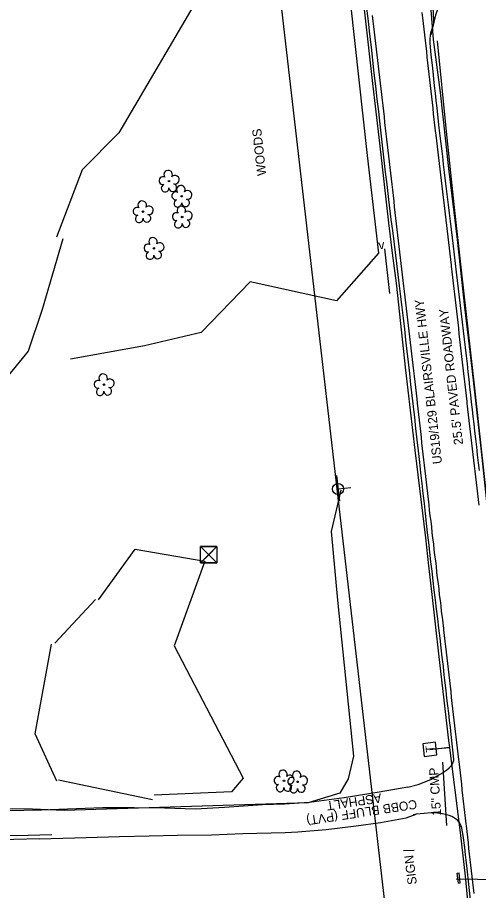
# Model space of a CAD drawing. Extents: x 472260 to 482161, y 489063 to 507124.
# Drawn here: x 478065.1 to 478267.5, y 496195.4 to 496579.2 of the extents above; entities that cross this region are included whole.
import ezdxf

# ---------------------------------------------------------------- set-up
doc = ezdxf.new("R2010")
doc.units = 0
for name, color, linetype in [('Exist Structure Minor Drop Inlet Cogo Elevation', 7, 'Continuous'), ('Exist Structure Minor Pipes CMP 60 Inch Cogo Number', 7, 'Continuous'), ('Prop Drainage Structure Catch Basin Convert From Junction Box Label', 7, 'Continuous'), ('Prop Drainage Structure Catch Basin Grate 840 03E CELL', 7, 'Continuous'), ('Prop Drainage Structure Drop Inlet Grate 2 Narrow Slots and Sag Grates 840 24 CELL', 7, 'Continuous'), ('Prop Drainage Structure Drop Inlet Grate 2 Wide Slots and Flat Grates 840 20 Label', 7, 'Continuous'), ('Prop Drainage Structure Drop Inlet Grate 2 Wide Slots and Sag Grates 840 22 Label', 7, 'Continuous'), ('Prop Drainage Structure Pipe Plug CELL', 7, 'Continuous'), ('Prop Drainage Structure Pipe RCP 18in Class IV Label', 7, 'Continuous'), ('Prop Drainage Structure Pipe RCP 48in Class IV', 7, 'Continuous'), ('Prop Drainage Structure Pipe RCP 66in Class III', 7, 'Continuous'), ('Prop Drainage Structure Pipe RCP 66in Class IV', 7, 'Continuous'), ('Prop Drainage Structure Pipe Stub Out CELL', 7, 'Continuous'), ('Prop Drainage Structure Pipe Welded Steel 66in', 7, 'Continuous'), ('Prop Drainage Structure Plot Symbol 20 Scale', 7, 'Continuous'), ('Prop Drainage Structure Plot Symbol 50 Scale', 7, 'Continuous'), ('Prop Drainage Structure Plot Symbol 50 Scale CELL', 7, 'Continuous'), ('Prop Drainage Structure Tops and Inverts LABEL', 7, 'Continuous'), ('Prop Earthen Structure Base Ditch Lateral Detail Label', 7, 'Continuous'), ('Prop Earthen Structure Ditch Flow Line', 7, 'Continuous'), ('Prop Erosion Rip Rap Class B', 7, 'Continuous'), ('Prop Erosion Rip Rap Class II', 7, 'Continuous'), ('Prop Erosion Rip Rap Pad at Outlet Label', 7, 'Continuous'), ('Prop Erosion Rip Rap Single Stone CELL', 7, 'Continuous')]:
    doc.layers.add(name, color=color, linetype=linetype)

msp = doc.modelspace()

# ---------------------------------------------------------------- linework, layer by layer
at = {"layer": 'Exist Structure Minor Drop Inlet Cogo Elevation'}
msp.add_line((478244.7, 496030.8), (478097.62, 497308.11), dxfattribs=at)
at = {"layer": 'Exist Structure Minor Pipes CMP 60 Inch Cogo Number'}
msp.add_lwpolyline([(477932.09, 496214.52), (477944.82, 496215.37), (477961.02, 496215.65), (477978.35, 496216), (477999.41, 496216.05), (478022.93, 496218.78), (478044.03, 496220.19), (478064.48, 496219.57), (478080.22, 496219.93)], dxfattribs=at)
at = {"layer": 'Prop Drainage Structure Catch Basin Convert From Junction Box Label'}
for p, q in [((478246.1, 496257.34), (478254.92, 496258.36)), ((478254.96, 496258.08), (478246.1, 496257.34)), ((478259.57, 496220.81), (478254.96, 496258.08))]:
    msp.add_line(p, q, dxfattribs=at)
for points in [[(478254.92, 496258.36), (478254.53, 496261.32), (478250.25, 496298.09), (478247.03, 496326.76), (478245.65, 496338.15), (478244.35, 496350.45), (478239.77, 496389), (478235.62, 496424.12), (478231.44, 496462.29), (478229.82, 496475.54), (478228.2, 496488.92), (478224.18, 496523.91), (478220.99, 496551.51), (478217.77, 496580.16), (478214.42, 496608.18), (478212.13, 496627.19), (478209.7, 496647.59)], [(478283.71, 496258.37), (478282.21, 496271.3), (478277.76, 496309.54), (478274.64, 496336.75), (478271.51, 496363.67), (478268.7, 496389.81), (478264.75, 496424.89), (478261.58, 496451.75), (478258.26, 496481.61), (478254.56, 496512.84), (478250.76, 496546.21), (478247.81, 496569.51), (478243.84, 496619.43)], [(478267.43, 496148.97), (478264.33, 496175.43), (478261.85, 496201.74), (478259.57, 496220.81)]]:
    msp.add_lwpolyline(points, dxfattribs=at)
at = {"layer": 'Prop Drainage Structure Catch Basin Grate 840 03E CELL'}
for points in [[(478207.13, 496371.39), (478202.78, 496353.14), (478205.59, 496323.03), (478212.56, 496254.5), (478210.29, 496244.46), (478206.56, 496238.11), (478192.66, 496233.88), (478085.63, 496230.58)], [(478085.63, 496230.58), (478071.67, 496231.2), (478059.76, 496231.25), (478048.46, 496233.16), (478033.66, 496233.12), (478024.73, 496232.35), (477990.68, 496238.22), (477984.51, 496232.22), (477980.39, 496227.84), (477972.64, 496226.1), (477964.27, 496225.16), (477948.52, 496225.15), (477932.34, 496224.85)]]:
    msp.add_lwpolyline(points, dxfattribs=at)
at = {"layer": 'Prop Drainage Structure Drop Inlet Grate 2 Narrow Slots and Sag Grates 840 24 CELL'}
for points in [[(478242.7, 496581.32), (478242.96, 496579.04), (478243.24, 496576.55), (478243.52, 496574.07), (478243.79, 496571.59), (478244.07, 496569.11), (478244.35, 496566.62), (478244.63, 496564.14), (478244.9, 496561.66), (478245.18, 496559.18), (478245.46, 496556.69), (478245.74, 496554.21), (478246.02, 496551.73), (478246.29, 496549.25), (478246.57, 496546.76), (478246.85, 496544.28), (478247.13, 496541.8), (478247.4, 496539.32), (478247.68, 496536.83), (478247.96, 496534.35), (478248.24, 496531.87), (478248.52, 496529.39), (478248.74, 496527.37), (478249.03, 496524.89), (478249.33, 496522.41), (478249.62, 496519.93), (478249.91, 496517.45), (478250.21, 496514.97), (478250.5, 496512.49), (478250.79, 496510.01), (478251.09, 496507.53), (478251.38, 496505.05), (478251.67, 496502.57), (478251.97, 496500.09), (478252.26, 496497.61), (478252.55, 496495.13), (478252.85, 496492.65), (478253.14, 496490.17), (478253.43, 496487.69), (478253.73, 496485.21), (478254.02, 496482.73), (478254.31, 496480.25), (478254.61, 496477.77), (478254.9, 496475.28), (478255.19, 496472.8), (478255.49, 496470.32), (478255.54, 496469.87), (478255.83, 496467.38), (478256.11, 496464.9), (478256.39, 496462.42), (478256.68, 496459.94), (478256.96, 496457.46), (478257.25, 496454.97), (478257.53, 496452.49), (478257.82, 496450.01), (478258.1, 496447.53), (478258.38, 496445.05), (478258.67, 496442.56), (478258.95, 496440.08), (478259.24, 496437.6), (478259.52, 496435.12), (478259.81, 496432.64), (478260.09, 496430.16), (478260.37, 496427.67), (478260.66, 496425.19), (478260.94, 496422.71), (478261.23, 496420.23), (478261.51, 496417.75), (478261.8, 496415.26), (478262.08, 496412.78), (478262.36, 496410.3), (478262.46, 496409.44), (478262.75, 496406.95), (478263.04, 496404.47), (478263.32, 496401.99), (478263.61, 496399.51), (478263.9, 496397.03), (478264.19, 496394.54), (478264.47, 496392.06), (478264.76, 496389.58), (478265.05, 496387.1), (478265.33, 496384.62), (478265.62, 496382.13), (478265.91, 496379.65), (478266.19, 496377.17), (478266.48, 496374.69), (478266.77, 496372.21), (478267.06, 496369.73), (478267.34, 496367.24), (478267.63, 496364.76)], [(478265.58, 496194.04), (478265.3, 496196.52), (478265.02, 496199.01), (478264.74, 496201.49), (478264.46, 496203.97), (478264.18, 496206.45), (478263.9, 496208.94), (478263.62, 496211.42), (478263.34, 496213.9), (478263.06, 496216.38), (478262.79, 496218.87), (478262.51, 496221.35), (478262.23, 496223.83), (478262.13, 496224.71), (478261.84, 496227.2), (478261.55, 496229.68), (478261.27, 496232.16), (478260.98, 496234.64), (478260.7, 496237.13), (478260.41, 496239.61), (478260.13, 496242.09), (478259.84, 496244.57), (478259.56, 496247.06), (478259.27, 496249.54), (478258.98, 496252.02), (478258.88, 496252.93), (478258.59, 496255.41), (478258.31, 496257.9), (478258.02, 496260.38), (478257.73, 496262.86), (478257.45, 496265.34), (478257.16, 496267.82), (478256.87, 496270.3), (478256.58, 496272.79), (478256.3, 496275.27), (478256.01, 496277.75), (478255.72, 496280.23), (478255.44, 496282.71), (478255.15, 496285.2), (478254.86, 496287.68), (478254.58, 496290.16), (478254.29, 496292.64), (478254, 496295.12), (478253.72, 496297.6), (478253.43, 496300.09), (478253.14, 496302.57), (478252.85, 496305.05), (478252.57, 496307.53), (478252.28, 496310.01), (478252.22, 496310.53), (478251.93, 496313.01), (478251.64, 496315.49), (478251.34, 496317.97), (478251.05, 496320.45), (478250.76, 496322.93), (478250.46, 496325.42), (478250.17, 496327.9), (478249.88, 496330.38), (478249.58, 496332.86), (478249.29, 496335.34), (478249, 496337.82), (478248.71, 496340.3), (478248.41, 496342.78), (478248.12, 496345.26), (478247.83, 496347.74), (478247.53, 496350.23), (478247.24, 496352.71), (478246.95, 496355.19), (478246.66, 496357.67), (478246.36, 496360.15), (478246.07, 496362.63), (478245.8, 496364.92), (478245.52, 496367.4), (478245.24, 496369.88), (478244.95, 496372.36), (478244.67, 496374.84), (478244.39, 496377.33), (478244.11, 496379.81), (478243.83, 496382.29), (478243.54, 496384.77), (478243.26, 496387.26), (478242.98, 496389.74), (478242.7, 496392.22), (478242.42, 496394.7), (478242.13, 496397.18), (478241.85, 496399.67), (478241.57, 496402.15), (478241.29, 496404.63), (478241.01, 496407.11), (478240.72, 496409.6), (478240.51, 496411.49), (478240.22, 496413.97), (478239.93, 496416.45), (478239.64, 496418.93), (478239.35, 496421.41), (478239.06, 496423.89), (478238.76, 496426.37), (478238.47, 496428.85), (478238.18, 496431.33), (478237.89, 496433.82), (478237.6, 496436.3), (478237.31, 496438.78), (478237.02, 496441.26), (478236.73, 496443.74), (478236.44, 496446.22), (478236.15, 496448.7), (478235.86, 496451.18), (478235.57, 496453.66), (478235.27, 496456.14), (478234.98, 496458.63), (478234.69, 496461.11), (478234.4, 496463.59), (478234.11, 496466.07), (478233.82, 496468.58), (478233.53, 496471.06), (478233.25, 496473.54), (478232.97, 496476.02), (478232.68, 496478.5), (478232.4, 496480.98), (478232.12, 496483.47), (478231.83, 496485.95), (478231.55, 496488.43), (478231.26, 496490.91), (478230.98, 496493.39), (478230.7, 496495.87), (478230.41, 496498.36), (478230.13, 496500.84), (478229.85, 496503.32), (478229.56, 496505.8), (478229.28, 496508.28), (478229, 496510.76), (478228.71, 496513.25), (478228.43, 496515.73), (478228.14, 496518.21), (478227.86, 496520.69), (478227.58, 496523.17), (478227.29, 496525.65), (478227.03, 496528), (478226.74, 496530.48), (478226.45, 496532.96), (478226.17, 496535.44), (478225.88, 496537.92), (478225.59, 496540.4), (478225.31, 496542.88), (478225.02, 496545.37), (478224.73, 496547.85), (478224.45, 496550.33), (478224.16, 496552.81), (478223.87, 496555.29), (478223.59, 496557.77), (478223.3, 496560.25), (478223.01, 496562.73), (478222.72, 496565.22), (478222.44, 496567.7), (478222.15, 496570.18), (478221.86, 496572.66), (478221.58, 496575.14), (478221.3, 496577.53), (478221.02, 496580.01)]]:
    msp.add_lwpolyline(points, dxfattribs=at)
at = {"layer": 'Prop Drainage Structure Drop Inlet Grate 2 Wide Slots and Flat Grates 840 20 Label'}
for p, q in [((478131.62, 496507.23), (478131.62, 496507.23)), ((478137.21, 496500.59), (478137.21, 496500.59)), ((478120.22, 496493.8), (478120.22, 496493.8)), ((478137.39, 496491.47), (478137.39, 496491.47)), ((478124.98, 496477.67), (478124.98, 496477.67)), ((478103.08, 496417.76), (478103.08, 496417.76)), ((478182.08, 496243.59), (478182.08, 496243.59)), ((478188.05, 496243.15), (478188.05, 496243.15))]:
    msp.add_line(p, q, dxfattribs=at)
for centre in [(478131.62, 496507.23), (478137.21, 496500.59), (478120.22, 496493.8), (478137.39, 496491.47), (478124.98, 496477.67), (478103.08, 496417.76), (478182.08, 496243.59), (478188.05, 496243.15)]:
    msp.add_circle(centre, 0.326, dxfattribs=at)
for centre, radius, start, end in [((478131.23, 496510.1), 1.86, 330.1651, 219.7134), ((478129.01, 496507.38), 1.73, 62.6636, 279.3457), ((478134.17, 496507.82), 1.9, 257.1011, 134.1999), ((478129.91, 496504.11), 1.69, 111.5671, 6.231), ((478133.29, 496504.33), 1.7, 181.2822, 74.56), ((478136.82, 496503.47), 1.86, 330.1651, 219.7134), ((478134.6, 496500.75), 1.73, 62.6636, 279.3457), ((478139.76, 496501.18), 1.9, 257.1011, 134.1999), ((478119.83, 496496.67), 1.86, 330.1651, 219.7134), ((478135.5, 496497.47), 1.69, 111.5671, 6.231), ((478138.88, 496497.69), 1.7, 181.2822, 74.56), ((478117.61, 496493.95), 1.73, 62.6636, 279.3457), ((478122.77, 496494.39), 1.9, 257.1011, 134.1999), ((478134.79, 496491.62), 1.73, 62.6636, 279.3457), ((478137.01, 496494.34), 1.86, 330.1651, 219.7134), ((478139.94, 496492.06), 1.9, 257.1011, 134.1999), ((478118.51, 496490.68), 1.69, 111.5671, 6.231), ((478121.89, 496490.9), 1.7, 181.2822, 74.56), ((478135.69, 496488.35), 1.69, 111.5671, 6.231), ((478139.07, 496488.57), 1.7, 181.2822, 74.56), ((478124.59, 496480.55), 1.86, 330.1651, 219.7134), ((478122.37, 496477.83), 1.73, 62.6636, 279.3457), ((478127.53, 496478.26), 1.9, 257.1011, 134.1999), ((478123.27, 496474.55), 1.69, 111.5671, 6.231), ((478126.65, 496474.77), 1.7, 181.2822, 74.56), ((478102.7, 496420.63), 1.86, 330.1651, 219.7134), ((478105.63, 496418.35), 1.9, 257.1011, 134.1999), ((478100.47, 496417.91), 1.73, 62.6636, 279.3457), ((478101.38, 496414.64), 1.69, 111.5671, 6.231), ((478104.75, 496414.86), 1.7, 181.2822, 74.56), ((478181.69, 496246.46), 1.86, 330.1651, 219.7134), ((478187.66, 496246.03), 1.86, 330.1651, 219.7134), ((478179.47, 496243.74), 1.73, 62.6636, 279.3457), ((478184.62, 496244.18), 1.9, 257.1011, 134.1999), ((478185.44, 496243.31), 1.73, 62.6636, 279.3457), ((478190.6, 496243.74), 1.9, 257.1011, 134.1999), ((478180.37, 496240.47), 1.69, 111.5671, 6.231), ((478183.75, 496240.69), 1.7, 181.2822, 74.56), ((478186.34, 496240.03), 1.69, 111.5671, 6.231), ((478189.72, 496240.25), 1.7, 181.2822, 74.56)]:
    msp.add_arc(centre, radius, start, end, dxfattribs=at)
at = {"layer": 'Prop Drainage Structure Pipe Plug CELL'}
msp.add_line((478239.25, 496213.02), (478234.56, 496212.82), dxfattribs=at)
at = {"layer": 'Prop Drainage Structure Pipe RCP 66in Class IV'}
msp.add_line((478257.64, 496200.47), (478313.98, 496199.54), dxfattribs=at)
at = {"layer": 'Prop Drainage Structure Pipe Stub Out CELL'}
for points in [[(478236.44, 496240.8), (478241.02, 496241.98), (478242.19, 496242.4), (478246.87, 496244.28), (478251.67, 496247.04), (478253.48, 496248.33), (478254.7, 496249.35), (478255.1, 496249.74), (478255.64, 496250.39), (478256.11, 496251.04), (478256.31, 496251.4), (478256.46, 496251.79), (478256.58, 496252.22), (478256.65, 496252.68), (478256.67, 496253.18), (478256.11, 496258.57), (478255.5, 496264), (478255.16, 496267), (478254.8, 496270.1), (478254.43, 496273.31), (478254.05, 496276.59), (478253.67, 496279.91), (478253.29, 496283.26), (478252.91, 496286.65), (478252.51, 496290.17), (478252.09, 496293.91), (478251.63, 496297.88), (478251.14, 496302.08), (478250.64, 496306.37), (478250.14, 496310.63), (478249.63, 496314.85), (478249.12, 496319.04), (478248.62, 496323.21), (478248.12, 496327.38), (478247.62, 496331.54), (478247.13, 496335.7), (478246.64, 496339.87), (478246.16, 496344.07), (478245.67, 496348.29), (478245.19, 496352.54), (478244.71, 496356.82), (478244.22, 496361.13), (478243.73, 496365.48), (478243.24, 496369.86), (478242.74, 496374.33), (478242.22, 496378.95), (478241.69, 496383.71), (478241.14, 496388.6), (478240.59, 496393.56), (478240.04, 496398.46), (478239.49, 496403.33), (478238.94, 496408.16), (478238.39, 496412.98), (478237.84, 496417.83), (478237.3, 496422.7), (478236.76, 496427.61), (478236.22, 496432.51), (478235.67, 496437.36), (478235.13, 496442.16), (478234.59, 496446.92), (478234.03, 496451.67), (478233.46, 496456.45), (478232.88, 496461.26), (478232.27, 496466.1), (478231.66, 496470.94), (478231.05, 496475.79), (478230.44, 496480.63), (478229.83, 496485.46), (478229.21, 496490.35), (478228.59, 496495.37), (478227.97, 496500.51), (478227.35, 496505.77), (478226.73, 496511.09), (478226.12, 496516.4), (478225.51, 496521.7), (478224.91, 496526.99), (478224.31, 496532.32), (478223.69, 496537.76), (478223.06, 496543.31), (478222.41, 496548.97), (478221.76, 496554.68), (478221.11, 496560.39), (478220.46, 496566.1), (478219.81, 496571.81), (478219.16, 496577.52), (478218.5, 496583.26)], [(478247.42, 496583.58), (478247.81, 496578.07), (478247.74, 496576.9), (478247.56, 496575.82), (478246.43, 496572.21), (478246.26, 496571.37), (478246.08, 496569.68), (478246.08, 496568.05), (478246.62, 496562.59), (478247.1, 496558.25), (478247.41, 496555.37), (478247.75, 496552.23), (478248.1, 496549.05), (478248.45, 496545.84), (478248.81, 496542.59), (478249.16, 496539.4), (478249.5, 496536.34), (478250.16, 496530.64), (478250.85, 496524.78), (478251.23, 496521.54), (478251.64, 496518.08), (478252.07, 496514.52), (478252.49, 496510.97), (478252.92, 496507.42), (478253.35, 496503.87), (478253.77, 496500.32), (478254.2, 496496.76), (478254.63, 496493.2), (478255.06, 496489.63), (478255.49, 496486.02), (478255.93, 496482.33), (478256.38, 496478.58), (478256.84, 496474.76), (478257.3, 496470.94), (478257.74, 496467.18), (478258.18, 496463.49), (478258.61, 496459.87), (478259.04, 496456.26), (478259.47, 496452.61), (478259.92, 496448.92), (478260.38, 496445.2), (478260.84, 496441.47), (478261.28, 496437.77), (478261.7, 496434.11), (478262.11, 496430.48), (478262.51, 496426.9), (478262.89, 496423.4), (478263.26, 496419.96), (478263.62, 496416.6), (478263.97, 496413.3), (478264.33, 496410.05), (478264.69, 496406.85), (478265.05, 496403.7), (478265.42, 496400.52), (478265.8, 496397.24), (478266.19, 496393.86), (478266.58, 496390.37), (478266.98, 496386.85), (478267.37, 496383.39), (478267.76, 496380)], [(478236.44, 496240.8), (478223.92, 496238.63), (478208.46, 496236.09), (478193.22, 496234.13), (478182.34, 496233.34), (478172.59, 496233.07), (478156, 496231.93), (478143.27, 496231.15), (478129.63, 496231.57), (478116.33, 496231.74), (478102.38, 496231.66), (478075.59, 496230.75)], [(478075.59, 496230.75), (478028.62, 496229.82), (477993.6, 496227.57), (477960.9, 496227.1), (477934.63, 496226.43)], [(478074.8, 496218.14), (478095.26, 496218.68), (478109.93, 496219.12), (478122.87, 496219.43), (478135.39, 496219.7), (478150.29, 496219.81), (478164.07, 496220.51), (478182.61, 496220.86), (478188.19, 496221.11), (478200.59, 496222.22), (478213.8, 496223.77), (478224.41, 496225.3), (478235.71, 496227.33), (478240.19, 496228.9)], [(478264.06, 496191.15), (478263.59, 496195.36), (478263.13, 496199.52), (478262.67, 496203.62), (478262.23, 496207.52), (478261.83, 496211.07), (478261.45, 496214.26), (478260.8, 496219.52), (478260.23, 496222.78), (478259.97, 496223.62), (478259.49, 496224.64), (478259.08, 496225.35), (478258.86, 496225.63), (478258.25, 496226.26), (478257.44, 496226.93), (478256.61, 496227.5), (478255.74, 496227.96), (478254.65, 496228.37), (478251.74, 496229.08), (478248.34, 496229.51), (478246.76, 496229.53), (478243.69, 496229.29), (478240.19, 496228.9), (478238.79, 496228.7)], [(478074.8, 496218.14), (478029.49, 496216.87), (477994.23, 496215.35), (477961.88, 496214.52), (477934.84, 496214.07)]]:
    msp.add_lwpolyline(points, dxfattribs=at)
at = {"layer": 'Prop Drainage Structure Pipe Welded Steel 66in'}
msp.add_line((478149.09, 496342.98), (478149.09, 496342.98), dxfattribs=at)
msp.add_lwpolyline([(478145.49, 496346.57), (478152.68, 496346.57), (478152.68, 496339.39), (478145.49, 496339.39)], close=True, dxfattribs=at)
for points in [[(478152.68, 496346.57), (478145.49, 496339.39), (478149.09, 496342.98), (478152.68, 496339.39), (478145.49, 496346.57)], [(478149.09, 496342.98), (478152.68, 496346.57), (478145.49, 496346.57), (478149.09, 496342.98)], [(478149.09, 496342.98), (478145.49, 496339.39), (478152.68, 496339.39), (478149.09, 496342.98)]]:
    msp.add_lwpolyline(points, dxfattribs=at)
at = {"layer": 'Prop Drainage Structure Plot Symbol 20 Scale'}
msp.add_line((478228.54, 496457.81), (478226.4, 496477.46), dxfattribs=at)
at = {"layer": 'Prop Drainage Structure Plot Symbol 50 Scale'}
for p, q in [((478258.16, 496203), (478258.99, 496203.1)), ((478258.66, 496198.6), (478258.16, 496203)), ((478259.48, 496198.7), (478258.99, 496203.1)), ((478258.66, 496198.6), (478259.48, 496198.7))]:
    msp.add_line(p, q, dxfattribs=at)
at = {"layer": 'Prop Drainage Structure Plot Symbol 50 Scale CELL'}
msp.add_lwpolyline([(478249.4, 496568.86), (478253.32, 496529.06), (478256.65, 496497), (478260.06, 496466.83), (478265.67, 496417.48), (478270.32, 496374.68), (478274.6, 496334.65), (478279.87, 496289.32), (478285.61, 496239.91), (478290.24, 496199.44), (478296.25, 496146.09)], dxfattribs=at)
at = {"layer": 'Prop Drainage Structure Tops and Inverts LABEL'}
msp.add_lwpolyline([(478204.01, 496651.61), (478218.61, 496518.46), (478223.64, 496475.62), (478205.09, 496454.64), (478167.18, 496462.99), (478145.75, 496440.73), (478120.83, 496434.88), (478088.4, 496428.93)], dxfattribs=at)
at = {"layer": 'Prop Earthen Structure Base Ditch Lateral Detail Label'}
msp.add_line((478205.84, 496371.89), (478205.84, 496371.89), dxfattribs=at)
msp.add_lwpolyline([(478205.17, 496377.79), (478206.41, 496366.52), (478205.82, 496371.89), (478211.43, 496372.53)], dxfattribs=at)
msp.add_circle((478205.85, 496371.89), 2.45, dxfattribs=at)
at = {"layer": 'Prop Earthen Structure Ditch Flow Line'}
msp.add_lwpolyline([(478407.46, 496611.74), (478397.75, 496611.35), (478385.59, 496610.99), (478370.44, 496611.13), (478353.49, 496610.82), (478342.54, 496610.77), (478324.72, 496609.73), (478303.17, 496608.56), (478283.23, 496607.51), (478271.21, 496605.99), (478267.2, 496604.43), (478263.27, 496602.55), (478258.69, 496599.54), (478256.65, 496597.71), (478254.81, 496595.18), (478253.25, 496593.06), (478251.97, 496589.84), (478250.04, 496584.31), (478248.6, 496580.18), (478246.64, 496571.6)], dxfattribs=at)
at = {"layer": 'Prop Erosion Rip Rap Class B'}
msp.add_line((478246.1, 496257.34), (478246.1, 496257.34), dxfattribs=at)
msp.add_lwpolyline([(478249.21, 496254.96), (478248.57, 496260.52), (478243.02, 496259.88), (478243.66, 496254.32), (478249.21, 496254.96)], dxfattribs=at)
at = {"layer": 'Prop Erosion Rip Rap Pad at Outlet Label'}
for p, q in [((478081.53, 496304.07), (478099.3, 496323.3)), ((478124.42, 496235.29), (478083.06, 496243.83))]:
    msp.add_line(p, q, dxfattribs=at)
for points in [[(478067.75, 496608.04), (478117.36, 496603.45), (478177.88, 496589.88), (478177.8, 496586.07), (478142.44, 496584.63), (478109.62, 496528.51), (478093.53, 496512.14), (478082.21, 496482.6)], [(478085.01, 496481.84), (478075.85, 496450.75), (478069.76, 496432.41), (478056.45, 496416.3)], [(478100.6, 496323.12), (478116.73, 496345.43), (478147.32, 496340.13), (478133.93, 496302.88), (478164.17, 496244.8), (478158.98, 496238.81), (478125.08, 496237.34)], [(478082.28, 496243.48), (478072.79, 496264.32), (478079.94, 496303.68)]]:
    msp.add_lwpolyline(points, dxfattribs=at)
at = {"layer": 'Prop Erosion Rip Rap Single Stone CELL'}
msp.add_line((478251.69, 496251.83), (478253.51, 496224), dxfattribs=at)

# ---------------------------------------------------------------- texts
at = {"layer": 'Prop Drainage Structure Drop Inlet Grate 2 Wide Slots and Sag Grates 840 22 Label'}
for s, rotation, p in [('US19/129 BLAIRSVILLE HWY', 96.3583, (478251.5, 496383.07)), ("25.5' PAVED ROADWAY", 96.3583, (478260.76, 496391.52)), ('ASPHALT', 188.6296, (478224.62, 496238.11)), ('COBB BLUFF (PVT)', 188.6296, (478240.19, 496235.34))]:
    msp.add_text(s, height=4, rotation=rotation, dxfattribs=at).set_placement(p)
at = {"layer": 'Prop Drainage Structure Pipe RCP 18in Class IV Label'}
msp.add_text('v', height=4, rotation=6.2173, dxfattribs=at).set_placement((478223.77, 496477.17))
at = {"layer": 'Prop Drainage Structure Pipe RCP 48in Class IV'}
msp.add_text('SIGN', height=4, rotation=97.12, dxfattribs=at).set_placement((478240.46, 496198.18))
at = {"layer": 'Prop Drainage Structure Pipe RCP 66in Class III'}
msp.add_text('WOODS', height=4, rotation=96.3583, dxfattribs=at).set_placement((478174.37, 496509.8))
at = {"layer": 'Prop Erosion Rip Rap Class B'}
msp.add_text('T', height=3.42, rotation=96.5673, dxfattribs=at).set_placement((478247.93, 496256.41))
at = {"layer": 'Prop Erosion Rip Rap Class II'}
msp.add_text('15" CMP', height=4, rotation=93.736, dxfattribs=at).set_placement((478251.15, 496228.37))

doc.saveas('drawing.dxf')
